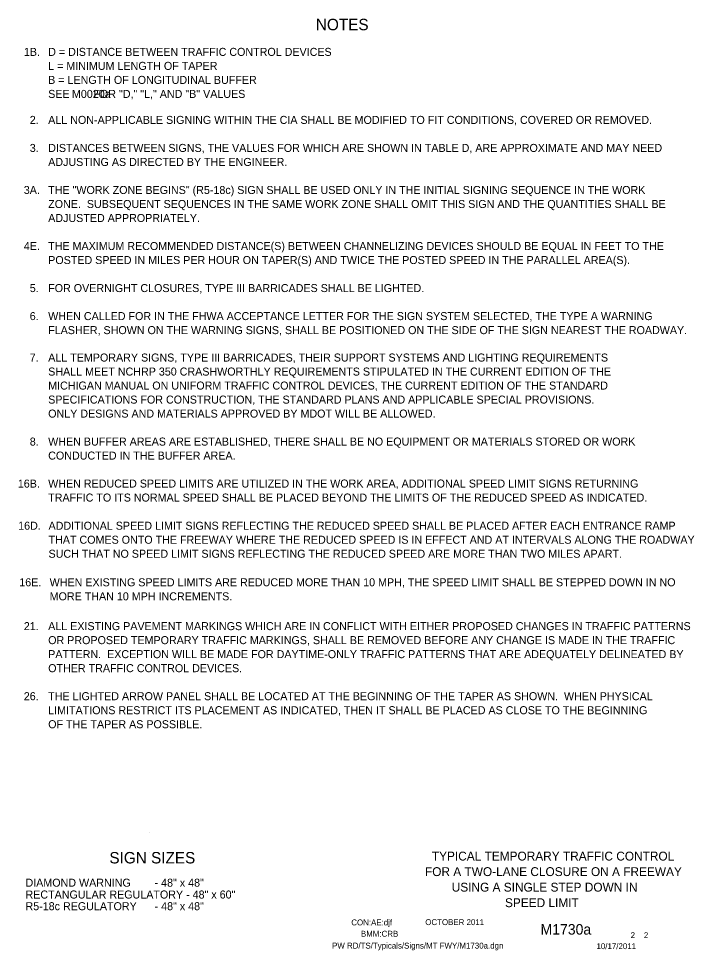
# Model space of a CAD drawing. Extents: x 16735 to 18480, y 5523 to 6928.
# Drawn here: x 17771 to 18480, y 5932 to 6909 of the extents above; entities that cross this region are included whole.
import ezdxf

# ---------------------------------------------------------------- set-up
doc = ezdxf.new("R2010")
doc.units = 0
for name, color, linetype in [('BORDER', 7, 'Continuous'), ('BORDER_SIGNAL_WO', 7, 'Continuous'), ('TYPICAL_TEXT_DIMEN_PR', 7, 'Continuous')]:
    doc.layers.add(name, color=color, linetype=linetype)

msp = doc.modelspace()

# ---------------------------------------------------------------- linework, layer by layer
at = {"layer": 'BORDER'}
for p, q in [((17907.48, 6055), (17907.48, 6055)), ((17907.48, 6035.02), (17907.48, 6035.02))]:
    msp.add_line(p, q, dxfattribs=at)

# ---------------------------------------------------------------- texts
for s, p in [('TYPICAL TEMPORARY TRAFFIC CONTROL', (18204.21, 6026.08)), ('FOR A TWO-LANE CLOSURE ON A FREEWAY', (18196.99, 6009.78)), ('USING A SINGLE STEP DOWN IN', (18225.04, 5993.48)), ('SPEED LIMIT', (18280.92, 5977.18))]:
    msp.add_text(s, height=9.3, dxfattribs=at).set_placement(p)
at = {"layer": 'BORDER_SIGNAL_WO'}
for s, height, p in [('CON:AE:djf  ', 6.2, (18119.69, 5958.06)), ('    OCTOBER 2011', 6.2, (18188.08, 5958.34)), ('BMM:CRB', 6.2, (18129.81, 5946.17)), ('    M1730a   ', 11, (18301.86, 5948.38)), (' 2    2 ', 6.2, (18410.45, 5944.7)), ('PW RD/TS/Typicals/Signs/MT FWY/M1730a.dgn      ', 6.2, (18099.55, 5933.71)), ('10/17/2011', 6.2, (18376.93, 5933.13))]:
    msp.add_text(s, height=height, dxfattribs=at).set_placement(p)
at = {"layer": 'TYPICAL_TEXT_DIMEN_PR'}
for s, height, p in [('NOTES', 12, (18082.55, 6897)), ('1B.', 8.4, (17776.19, 6870.11)), ('D = DISTANCE BETWEEN TRAFFIC CONTROL DEVICES', 8.4, (17801.7, 6870.11)), ('L = MINIMUM LENGTH OF TAPER', 8.4, (17801.7, 6855.41)), ('B = LENGTH OF LONGITUDINAL BUFFER', 8.4, (17801.7, 6840.71)), ('SEE        FOR "D," "L," AND "B" VALUES', 8.4, (17801.7, 6826.01)), ('M0020a', 8.4, (17826.62, 6826.01)), ('2.', 8.4, (17782.39, 6798.75)), ('ALL NON-APPLICABLE SIGNING WITHIN THE CIA SHALL BE MODIFIED TO FIT CONDITIONS, COVERED OR REMOVED.', 8.4, (17801.7, 6798.75)), ('3.', 8.4, (17782.39, 6769.35)), ('DISTANCES BETWEEN SIGNS, THE VALUES FOR WHICH ARE SHOWN IN TABLE D, ARE APPROXIMATE AND MAY NEED', 8.4, (17801.7, 6769.35)), ('ADJUSTING AS DIRECTED BY THE ENGINEER.', 8.4, (17801.7, 6754.65)), ('THE "WORK ZONE BEGINS" (R5-18c) SIGN SHALL BE USED ONLY IN THE INITIAL SIGNING SEQUENCE IN THE WORK', 8.4, (17801.7, 6725.25)), ('3A.', 8.4, (17776.09, 6725.25)), ('ZONE.  SUBSEQUENT SEQUENCES IN THE SAME WORK ZONE SHALL OMIT THIS SIGN AND THE QUANTITIES SHALL BE', 8.4, (17801.7, 6710.55)), ('ADJUSTED APPROPRIATELY.', 8.4, (17801.7, 6695.85)), ('THE MAXIMUM RECOMMENDED DISTANCE(S) BETWEEN CHANNELIZING DEVICES SHOULD BE EQUAL IN FEET TO THE', 8.4, (17801.7, 6666.45)), ('4E.', 8.4, (17776.13, 6666.45)), ('POSTED SPEED IN MILES PER HOUR ON TAPER(S) AND TWICE THE POSTED SPEED IN THE PARALLEL AREA(S).', 8.4, (17801.7, 6651.75)), ('5.', 8.4, (17782.39, 6622.35)), ('FOR OVERNIGHT CLOSURES, TYPE III BARRICADES SHALL BE LIGHTED.', 8.4, (17801.7, 6622.35)), ('6.', 8.4, (17782.34, 6592.95)), ('WHEN CALLED FOR IN THE FHWA ACCEPTANCE LETTER FOR THE SIGN SYSTEM SELECTED, THE TYPE A WARNING ', 8.4, (17801.7, 6592.95)), ('FLASHER, SHOWN ON THE WARNING SIGNS, SHALL BE POSITIONED ON THE SIDE OF THE SIGN NEAREST THE ROADWAY.', 8.4, (17801.7, 6578.25)), ('ALL TEMPORARY SIGNS, TYPE III BARRICADES, THEIR SUPPORT SYSTEMS AND LIGHTING REQUIREMENTS', 8.4, (17801.7, 6549.48)), ('7.', 8.4, (17782.34, 6549.46)), ('SHALL MEET NCHRP 350 CRASHWORTHLY REQUIREMENTS STIPULATED IN THE CURRENT EDITION OF THE', 8.4, (17801.7, 6534.78)), ('MICHIGAN MANUAL ON UNIFORM TRAFFIC CONTROL DEVICES, THE CURRENT EDITION OF THE STANDARD', 8.4, (17801.7, 6520.08)), ('SPECIFICATIONS FOR CONSTRUCTION, THE STANDARD PLANS AND APPLICABLE SPECIAL PROVISIONS.', 8.4, (17801.7, 6505.38)), ('ONLY DESIGNS AND MATERIALS APPROVED BY MDOT WILL BE ALLOWED.', 8.4, (17801.7, 6490.68)), ('8.', 8.4, (17782.39, 6461.34)), ('WHEN BUFFER AREAS ARE ESTABLISHED, THERE SHALL BE NO EQUIPMENT OR MATERIALS STORED OR WORK     ', 8.4, (17801.7, 6461.34)), ('CONDUCTED IN THE BUFFER AREA.', 8.4, (17801.7, 6446.64)), ('16B.', 8.4, (17769.84, 6417.24)), ('WHEN REDUCED SPEED LIMITS ARE UTILIZED IN THE WORK AREA, ADDITIONAL SPEED LIMIT SIGNS RETURNING', 8.4, (17801.7, 6417.3)), ('TRAFFIC TO ITS NORMAL SPEED SHALL BE PLACED BEYOND THE LIMITS OF THE REDUCED SPEED AS INDICATED.', 8.4, (17801.7, 6402.6)), ('16D.', 8.4, (17770.2, 6373.07)), ('ADDITIONAL SPEED LIMIT SIGNS REFLECTING THE REDUCED SPEED SHALL BE PLACED AFTER EACH ENTRANCE RAMP', 8.4, (17802.07, 6373.07)), ('THAT COMES ONTO THE FREEWAY WHERE THE REDUCED SPEED IS IN EFFECT AND AT INTERVALS ALONG THE ROADWAY', 8.4, (17802.07, 6358.37)), ('SUCH THAT NO SPEED LIMIT SIGNS REFLECTING THE REDUCED SPEED ARE MORE THAN TWO MILES APART.', 8.4, (17802.07, 6343.67)), ('16E.', 8.4, (17771.37, 6313.73)), ('WHEN EXISTING SPEED LIMITS ARE REDUCED MORE THAN 10 MPH, THE SPEED LIMIT SHALL BE STEPPED DOWN IN NO', 8.4, (17803.24, 6313.73)), ('MORE THAN 10 MPH INCREMENTS.', 8.4, (17803.24, 6299.03)), ('21.', 8.4, (17776.14, 6267.75)), ('ALL EXISTING PAVEMENT MARKINGS WHICH ARE IN CONFLICT WITH EITHER PROPOSED CHANGES IN TRAFFIC PATTERNS', 8.4, (17801.7, 6267.75)), ('OR PROPOSED TEMPORARY TRAFFIC MARKINGS, SHALL BE REMOVED BEFORE ANY CHANGE IS MADE IN THE TRAFFIC', 8.4, (17801.7, 6253.05)), ('PATTERN.  EXCEPTION WILL BE MADE FOR DAYTIME-ONLY TRAFFIC PATTERNS THAT ARE ADEQUATELY DELINEATED BY', 8.4, (17801.7, 6238.35)), ('OTHER TRAFFIC CONTROL DEVICES.', 8.4, (17801.7, 6223.65)), ('26.', 8.4, (17776.09, 6194.25)), ('THE LIGHTED ARROW PANEL SHALL BE LOCATED AT THE BEGINNING OF THE TAPER AS SHOWN.  WHEN PHYSICAL', 8.4, (17801.7, 6194.25)), ('LIMITATIONS RESTRICT ITS PLACEMENT AS INDICATED, THEN IT SHALL BE PLACED AS CLOSE TO THE BEGINNING', 8.4, (17801.7, 6179.55)), ('OF THE TAPER AS POSSIBLE.', 8.4, (17801.7, 6164.85)), ('SIGN SIZES', 12, (17865.92, 6023.02)), ('DIAMOND WARNING        - 48" x 48"', 8.4, (17777.88, 5998.62)), ('RECTANGULAR REGULATORY - 48" x 60"', 8.4, (17777.88, 5986.22)), ('R5-18c REGULATORY      - 48" x 48"', 8.4, (17777.88, 5973.96))]:
    msp.add_text(s, height=height, dxfattribs=at).set_placement(p)

doc.saveas('drawing.dxf')
